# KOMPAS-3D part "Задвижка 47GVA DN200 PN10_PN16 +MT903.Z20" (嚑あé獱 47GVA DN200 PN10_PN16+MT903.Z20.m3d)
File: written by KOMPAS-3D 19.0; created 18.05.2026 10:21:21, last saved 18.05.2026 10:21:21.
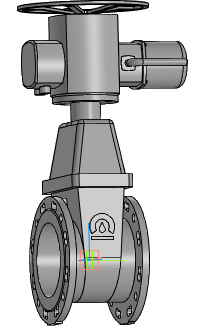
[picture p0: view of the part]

Document properties: Автор: Энергия; Полное имя файла: ..\Задвижка 47GVA DN50_DN1000+MT903.Z\Задвижка 47GVA DN200 PN10_PN16+MT903.Z20.a3d

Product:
- Part/product: Задвижка 47GVA DN200 PN10_PN16 +MT903.Z20
    Масса: 180.461
  - Body: Электропривод MT903.Z20-30
      Масса: 83.2154
  - Body: Задвижка 47GVA DN200 PN10_PN16 без исполнит. мех.
      Масса: 97.2454

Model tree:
1. Операция без истории:1
2. Операция без истории:2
